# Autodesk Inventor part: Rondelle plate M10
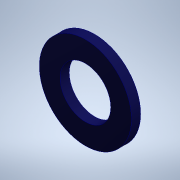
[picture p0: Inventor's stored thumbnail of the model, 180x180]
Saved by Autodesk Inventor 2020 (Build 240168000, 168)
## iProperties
Created: 2003-08
Part Number: Rondelle plate M10
Material: Générique
Document SubType Name: Modeling
Designer: Bruno
Density: 1 g/cm^3
Appearance: Par défaut
Author: Bruno
Sending System: SolidWorks 2011
Last Author: frederic
Last Saved: 2012-02-20
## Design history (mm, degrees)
feature "Base-Extrusion"
node "Solide1"
